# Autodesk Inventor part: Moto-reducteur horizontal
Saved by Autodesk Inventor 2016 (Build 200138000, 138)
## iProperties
Created: 2013-08
Part Number: Moto-reducteur horizontal
Material: Générique
Document SubType Name: Modeling
Designer: hilarion
Density: 1 g/cm^3
Appearance: Par défaut
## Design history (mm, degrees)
node "Moto-reducteur horizontal1"
node "Moto-reducteur horizontal"
node "Base1"
